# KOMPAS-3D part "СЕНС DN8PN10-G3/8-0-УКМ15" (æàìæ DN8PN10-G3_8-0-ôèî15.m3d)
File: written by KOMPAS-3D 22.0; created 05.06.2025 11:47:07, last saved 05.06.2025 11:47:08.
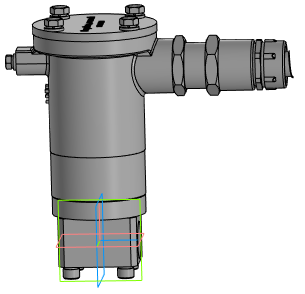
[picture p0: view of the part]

Document properties: Автор: setup; Полное имя файла: D:\WS127\D\Савин\!СЕНСОР\3D для заказчика\!Новый перечень\СЕНС\10. СЕНС-G(K)\СЕНС DN8PN10-G3_8-0-УКМ15.m3d

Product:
- Body: Тело 1
    Масса: 3.392226
- Part/product: СЕНС DN8PN10-G3/8-0-УКМ15
    Масса: 2.172437

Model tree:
1. Операция без истории:1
